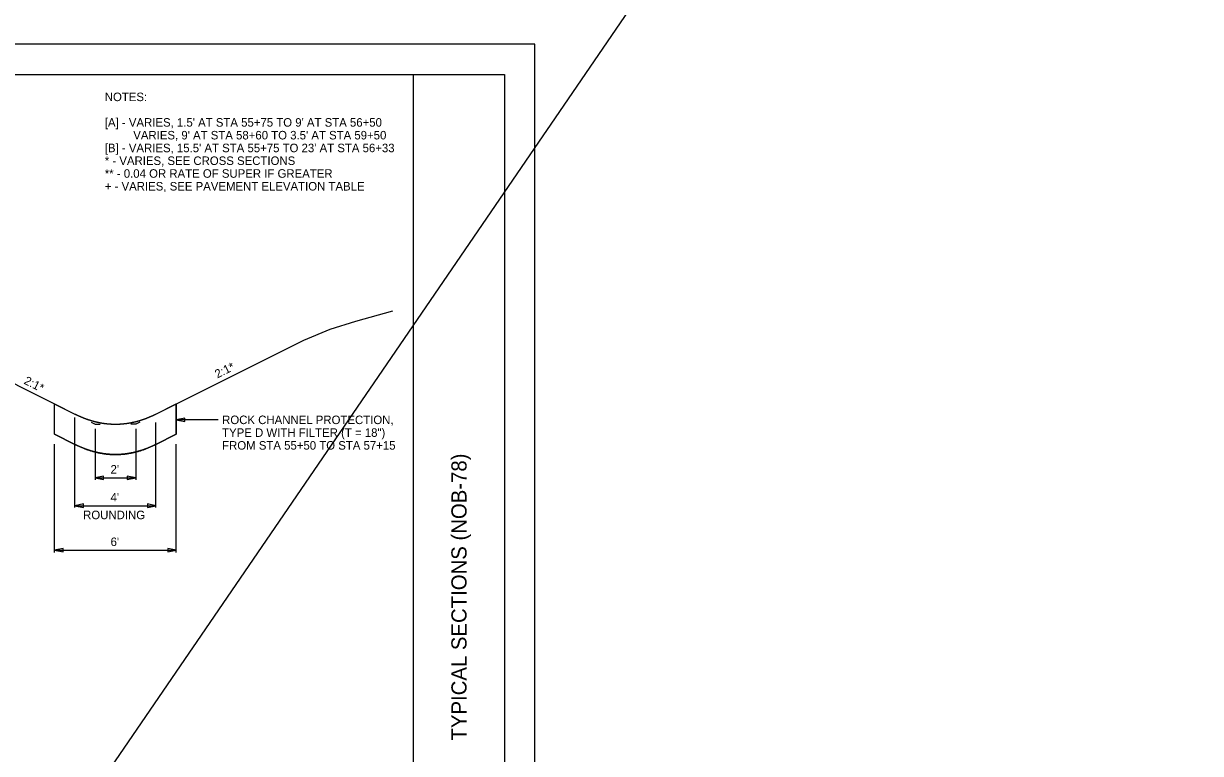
# Model space of a CAD drawing. Extents: x -345 to 102, y -108 to 100.
# Drawn here: x -258.4 to -200.3, y 21.8 to 57.8 of the extents above; entities that cross this region are included whole.
import ezdxf

# ---------------------------------------------------------------- set-up
doc = ezdxf.new("R2010")
doc.units = 0
for name, color, linetype in [('DR_P_Erosion_Control', 7, 'Continuous'), ('DT_X_Terrain_Ground_Line', 7, 'Continuous'), ('SH_Border', 7, 'Continuous'), ('SH_Cut_Line', 7, 'Continuous'), ('SH_Data', 7, 'Continuous'), ('TX_P_1', 7, 'Continuous'), ('TX_X_1', 7, 'Continuous'), ('XS_P_Finished_Grade', 7, 'Continuous')]:
    doc.layers.add(name, color=color, linetype=linetype)

msp = doc.modelspace()

# ---------------------------------------------------------------- linework, layer by layer
at = {"layer": 'DR_P_Erosion_Control'}
for p, q in [((-256.838, 37.548), (-256.838, 39.048)), ((-250.838, 37.548), (-250.838, 39.048)), ((-256.838, 37.548), (-255.838, 37.048)), ((-251.838, 37.048), (-250.838, 37.548))]:
    msp.add_line(p, q, dxfattribs=at)
for points in [[(-255.838, 37.048), (-256.838, 37.548), (-256.838, 39.048), (-255.838, 38.548)], [(-251.838, 38.548), (-250.838, 39.048), (-250.838, 37.548), (-251.838, 37.048)]]:
    msp.add_lwpolyline(points, dxfattribs=at)
for points in [[(-255.838, 38.548), (-255.813, 38.535), (-255.787, 38.523), (-255.761, 38.51), (-255.736, 38.498), (-255.71, 38.486), (-255.684, 38.474), (-255.659, 38.462), (-255.633, 38.451), (-255.607, 38.439), (-255.582, 38.428), (-255.556, 38.417), (-255.53, 38.406), (-255.505, 38.395), (-255.479, 38.385), (-255.453, 38.374), (-255.428, 38.364), (-255.402, 38.354), (-255.377, 38.344), (-255.351, 38.334), (-255.325, 38.324), (-255.3, 38.315), (-255.274, 38.306), (-255.248, 38.297), (-255.223, 38.288), (-255.197, 38.279), (-255.171, 38.27), (-255.146, 38.262), (-255.12, 38.253), (-255.095, 38.245), (-255.069, 38.237), (-255.043, 38.23), (-255.018, 38.222), (-254.992, 38.214), (-254.966, 38.207), (-254.941, 38.2), (-254.915, 38.193), (-254.889, 38.186), (-254.864, 38.179), (-254.838, 38.173), (-254.812, 38.167), (-254.787, 38.16), (-254.761, 38.155), (-254.736, 38.149), (-254.71, 38.143), (-254.684, 38.138), (-254.659, 38.132), (-254.633, 38.127), (-254.607, 38.122), (-254.582, 38.117), (-254.556, 38.112), (-254.53, 38.108), (-254.505, 38.104), (-254.479, 38.099), (-254.453, 38.095), (-254.428, 38.091), (-254.402, 38.088), (-254.377, 38.084), (-254.351, 38.081), (-254.325, 38.078), (-254.3, 38.075), (-254.274, 38.072), (-254.248, 38.069), (-254.223, 38.067), (-254.197, 38.064), (-254.171, 38.062), (-254.146, 38.06), (-254.12, 38.058), (-254.094, 38.056), (-254.069, 38.055), (-254.043, 38.053), (-254.018, 38.052), (-253.992, 38.051), (-253.966, 38.05), (-253.941, 38.049), (-253.915, 38.049), (-253.889, 38.048), (-253.864, 38.048), (-253.838, 38.048), (-253.812, 38.048), (-253.787, 38.048), (-253.761, 38.049), (-253.735, 38.049), (-253.71, 38.05), (-253.684, 38.051), (-253.659, 38.052), (-253.633, 38.053), (-253.607, 38.055), (-253.582, 38.056), (-253.556, 38.058), (-253.53, 38.06), (-253.505, 38.062), (-253.479, 38.064), (-253.453, 38.067), (-253.428, 38.069), (-253.402, 38.072), (-253.377, 38.075), (-253.351, 38.078), (-253.325, 38.081), (-253.3, 38.084), (-253.274, 38.088), (-253.248, 38.091), (-253.223, 38.095), (-253.197, 38.099), (-253.171, 38.104), (-253.146, 38.108), (-253.12, 38.112), (-253.094, 38.117), (-253.069, 38.122), (-253.043, 38.127), (-253.018, 38.132), (-252.992, 38.138), (-252.966, 38.143), (-252.941, 38.149), (-252.915, 38.155), (-252.889, 38.16), (-252.864, 38.167), (-252.838, 38.173), (-252.812, 38.179), (-252.787, 38.186), (-252.761, 38.193), (-252.735, 38.2), (-252.71, 38.207), (-252.684, 38.214), (-252.659, 38.222), (-252.633, 38.23), (-252.607, 38.237), (-252.582, 38.245), (-252.556, 38.253), (-252.53, 38.262), (-252.505, 38.27), (-252.479, 38.279), (-252.453, 38.288), (-252.428, 38.297), (-252.402, 38.306), (-252.377, 38.315), (-252.351, 38.324), (-252.325, 38.334), (-252.3, 38.344), (-252.274, 38.354), (-252.248, 38.364), (-252.223, 38.374), (-252.197, 38.385), (-252.171, 38.395), (-252.146, 38.406), (-252.12, 38.417), (-252.094, 38.428), (-252.069, 38.439), (-252.043, 38.451), (-252.017, 38.462), (-251.992, 38.474), (-251.966, 38.486), (-251.941, 38.498), (-251.915, 38.51), (-251.889, 38.523), (-251.864, 38.535), (-251.838, 38.548)], [(-251.838, 37.048), (-251.864, 37.035), (-251.889, 37.023), (-251.915, 37.01), (-251.941, 36.998), (-251.966, 36.986), (-251.992, 36.974), (-252.017, 36.962), (-252.043, 36.951), (-252.069, 36.939), (-252.094, 36.928), (-252.12, 36.917), (-252.146, 36.906), (-252.171, 36.895), (-252.197, 36.885), (-252.223, 36.874), (-252.248, 36.864), (-252.274, 36.854), (-252.3, 36.844), (-252.325, 36.834), (-252.351, 36.824), (-252.377, 36.815), (-252.402, 36.806), (-252.428, 36.797), (-252.453, 36.788), (-252.479, 36.779), (-252.505, 36.77), (-252.53, 36.762), (-252.556, 36.753), (-252.582, 36.745), (-252.607, 36.737), (-252.633, 36.73), (-252.659, 36.722), (-252.684, 36.714), (-252.71, 36.707), (-252.735, 36.7), (-252.761, 36.693), (-252.787, 36.686), (-252.812, 36.679), (-252.838, 36.673), (-252.864, 36.667), (-252.889, 36.66), (-252.915, 36.655), (-252.941, 36.649), (-252.966, 36.643), (-252.992, 36.638), (-253.018, 36.632), (-253.043, 36.627), (-253.069, 36.622), (-253.094, 36.617), (-253.12, 36.612), (-253.146, 36.608), (-253.171, 36.604), (-253.197, 36.599), (-253.223, 36.595), (-253.248, 36.591), (-253.274, 36.588), (-253.3, 36.584), (-253.325, 36.581), (-253.351, 36.578), (-253.377, 36.575), (-253.402, 36.572), (-253.428, 36.569), (-253.453, 36.567), (-253.479, 36.564), (-253.505, 36.562), (-253.53, 36.56), (-253.556, 36.558), (-253.582, 36.556), (-253.607, 36.555), (-253.633, 36.553), (-253.659, 36.552), (-253.684, 36.551), (-253.71, 36.55), (-253.735, 36.549), (-253.761, 36.549), (-253.787, 36.548), (-253.812, 36.548), (-253.838, 36.548), (-253.864, 36.548), (-253.889, 36.548), (-253.915, 36.549), (-253.941, 36.549), (-253.966, 36.55), (-253.992, 36.551), (-254.018, 36.552), (-254.043, 36.553), (-254.069, 36.555), (-254.094, 36.556), (-254.12, 36.558), (-254.146, 36.56), (-254.171, 36.562), (-254.197, 36.564), (-254.223, 36.567), (-254.248, 36.569), (-254.274, 36.572), (-254.3, 36.575), (-254.325, 36.578), (-254.351, 36.581), (-254.377, 36.584), (-254.402, 36.588), (-254.428, 36.591), (-254.453, 36.595), (-254.479, 36.599), (-254.505, 36.604), (-254.53, 36.608), (-254.556, 36.612), (-254.582, 36.617), (-254.607, 36.622), (-254.633, 36.627), (-254.659, 36.632), (-254.684, 36.638), (-254.71, 36.643), (-254.736, 36.649), (-254.761, 36.655), (-254.787, 36.66), (-254.812, 36.667), (-254.838, 36.673), (-254.864, 36.679), (-254.889, 36.686), (-254.915, 36.693), (-254.941, 36.7), (-254.966, 36.707), (-254.992, 36.714), (-255.018, 36.722), (-255.043, 36.73), (-255.069, 36.737), (-255.095, 36.745), (-255.12, 36.753), (-255.146, 36.762), (-255.171, 36.77), (-255.197, 36.779), (-255.223, 36.788), (-255.248, 36.797), (-255.274, 36.806), (-255.3, 36.815), (-255.325, 36.824), (-255.351, 36.834), (-255.377, 36.844), (-255.402, 36.854), (-255.428, 36.864), (-255.453, 36.874), (-255.479, 36.885), (-255.505, 36.895), (-255.53, 36.906), (-255.556, 36.917), (-255.582, 36.928), (-255.607, 36.939), (-255.633, 36.951), (-255.659, 36.962), (-255.684, 36.974), (-255.71, 36.986), (-255.736, 36.998), (-255.761, 37.01), (-255.787, 37.023), (-255.813, 37.035), (-255.838, 37.048)]]:
    msp.add_open_spline(points, degree=3, dxfattribs=at)
msp.add_spline([(-255.838, 37.048), (-255.761, 37.01), (-255.684, 36.974), (-255.607, 36.939), (-255.53, 36.906), (-255.453, 36.874), (-255.377, 36.844), (-255.3, 36.815), (-255.223, 36.788), (-255.146, 36.762), (-255.069, 36.737), (-254.992, 36.714), (-254.915, 36.693), (-254.838, 36.673), (-254.761, 36.655), (-254.684, 36.638), (-254.607, 36.622), (-254.53, 36.608), (-254.453, 36.595), (-254.377, 36.584), (-254.3, 36.575), (-254.223, 36.567), (-254.146, 36.56), (-254.069, 36.555), (-253.992, 36.551), (-253.915, 36.549), (-253.838, 36.548), (-253.761, 36.549), (-253.684, 36.551), (-253.607, 36.555), (-253.53, 36.56), (-253.453, 36.567), (-253.377, 36.575), (-253.3, 36.584), (-253.223, 36.595), (-253.146, 36.608), (-253.069, 36.622), (-252.992, 36.638), (-252.915, 36.655), (-252.838, 36.673), (-252.761, 36.693), (-252.684, 36.714), (-252.607, 36.737), (-252.53, 36.762), (-252.453, 36.788), (-252.377, 36.815), (-252.3, 36.844), (-252.223, 36.874), (-252.146, 36.906), (-252.069, 36.939), (-251.992, 36.974), (-251.915, 37.01), (-251.838, 37.048)], degree=3, dxfattribs=at)
at = {"layer": 'DT_X_Terrain_Ground_Line'}
msp.add_lwpolyline([(-244.547, 42.194), (-243.249, 42.729), (-241.974, 43.126), (-240.149, 43.631)], dxfattribs=at)
at = {"layer": 'SH_Border'}
msp.add_line((-239.144, -7.702), (-239.144, 55.298), dxfattribs=at)
msp.add_lwpolyline([(-330.644, 55.298), (-234.644, 55.298), (-234.644, -7.702), (-330.644, -7.702)], close=True, dxfattribs=at)
at = {"layer": 'SH_Cut_Line'}
msp.add_lwpolyline([(-335.144, -9.202), (-233.144, -9.202), (-233.144, 56.798), (-335.144, 56.798)], close=True, dxfattribs=at)
at = {"layer": 'TX_P_1'}
for p, q in [((-255.838, 33.931), (-255.838, 38.37)), ((-250.418, 38.176), (-250.418, 38.344)), ((-254.838, 37.81), (-254.838, 35.297)), ((-252.838, 37.81), (-252.838, 35.297)), ((-251.838, 33.931), (-251.838, 38.125)), ((-256.838, 31.71), (-256.838, 37.059)), ((-250.838, 31.71), (-250.838, 37.059)), ((-254.418, 35.316), (-254.418, 35.484)), ((-253.258, 35.484), (-253.258, 35.316)), ((-254.838, 35.4), (-252.838, 35.4)), ((-255.838, 34.025), (-251.838, 34.025)), ((-255.418, 33.941), (-255.418, 34.109)), ((-252.258, 34.109), (-252.258, 33.941)), ((-256.838, 31.825), (-250.838, 31.825)), ((-256.418, 31.741), (-256.418, 31.909)), ((-251.258, 31.909), (-251.258, 31.741))]:
    msp.add_line(p, q, dxfattribs=at)
for points in [[(-250.418, 38.344), (-250.838, 38.26), (-250.418, 38.176)], [(-255.041, 38.149), (-254.838, 38.048), (-254.596, 38.048)], [(-252.635, 38.149), (-252.838, 38.048), (-253.08, 38.048)], [(-254.418, 35.484), (-254.838, 35.4), (-254.418, 35.316)], [(-253.258, 35.316), (-252.838, 35.4), (-253.258, 35.484)], [(-255.418, 34.109), (-255.838, 34.025), (-255.418, 33.941)], [(-252.258, 33.941), (-251.838, 34.025), (-252.258, 34.109)], [(-256.418, 31.909), (-256.838, 31.825), (-256.418, 31.741)], [(-251.258, 31.741), (-250.838, 31.825), (-251.258, 31.909)]]:
    msp.add_lwpolyline(points, dxfattribs=at)
at = {"layer": 'TX_X_1'}
for p, q in [((-200.323, 99.689), (-335.9, -98.481)), ((-248.773, 38.26), (-250.838, 38.26))]:
    msp.add_line(p, q, dxfattribs=at)
at = {"layer": 'XS_P_Finished_Grade'}
for p, q in [((-251.838, 38.548), (-244.547, 42.194)), ((-260.075, 40.667), (-255.838, 38.548))]:
    msp.add_line(p, q, dxfattribs=at)
msp.add_spline([(-255.838, 38.548), (-255.761, 38.51), (-255.684, 38.474), (-255.607, 38.439), (-255.53, 38.406), (-255.453, 38.374), (-255.377, 38.344), (-255.3, 38.315), (-255.223, 38.288), (-255.146, 38.262), (-255.069, 38.237), (-254.992, 38.214), (-254.915, 38.193), (-254.838, 38.173), (-254.761, 38.155), (-254.684, 38.138), (-254.607, 38.122), (-254.53, 38.108), (-254.453, 38.095), (-254.377, 38.084), (-254.3, 38.075), (-254.223, 38.067), (-254.146, 38.06), (-254.069, 38.055), (-253.992, 38.051), (-253.915, 38.049), (-253.838, 38.048), (-253.761, 38.049), (-253.684, 38.051), (-253.607, 38.055), (-253.53, 38.06), (-253.453, 38.067), (-253.377, 38.075), (-253.3, 38.084), (-253.223, 38.095), (-253.146, 38.108), (-253.069, 38.122), (-252.992, 38.138), (-252.915, 38.155), (-252.838, 38.173), (-252.761, 38.193), (-252.684, 38.214), (-252.607, 38.237), (-252.53, 38.262), (-252.453, 38.288), (-252.377, 38.315), (-252.3, 38.344), (-252.223, 38.374), (-252.146, 38.406), (-252.069, 38.439), (-251.992, 38.474), (-251.915, 38.51), (-251.838, 38.548)], degree=3, dxfattribs=at)

# ---------------------------------------------------------------- texts
at = {"layer": 'SH_Data'}
msp.add_text('TYPICAL SECTIONS (NOB-78)', height=0.75, rotation=90, dxfattribs=at).set_placement((-236.519, 22.442))
at = {"layer": 'TX_P_1'}
for rotation, p in [(26.56505, (-248.81, 40.297)), (333.43495, (-258.386, 40.057))]:
    msp.add_text('2:1*', height=0.42, rotation=rotation, dxfattribs=at).set_placement(p)
for s, p in [("2'", (-254.077, 35.61)), ("4'", (-254.077, 34.235)), ('ROUNDING', (-255.432, 33.359)), ("6'", (-254.077, 32.035))]:
    msp.add_text(s, height=0.42, dxfattribs=at).set_placement(p)
at = {"layer": 'TX_X_1'}
for s, p in [('NOTES:', (-254.362, 53.983)), ("[A] - VARIES, 1.5' AT STA 55+75 TO 9' AT STA 56+50", (-254.362, 52.723)), ("         VARIES, 9' AT STA 58+60 TO 3.5' AT STA 59+50", (-254.362, 52.093)), ("[B] - VARIES, 15.5' AT STA 55+75 TO 23' AT STA 56+33", (-254.362, 51.463)), ('* - VARIES, SEE CROSS SECTIONS', (-254.362, 50.833)), ('** - 0.04 OR RATE OF SUPER IF GREATER', (-254.362, 50.203)), ('+ - VARIES, SEE PAVEMENT ELEVATION TABLE', (-254.362, 49.573)), ('ROCK CHANNEL PROTECTION,', (-248.575, 38.05)), ('TYPE D WITH FILTER (T = 18")', (-248.575, 37.42)), ('FROM STA 55+50 TO STA 57+15', (-248.575, 36.79))]:
    msp.add_text(s, height=0.42, dxfattribs=at).set_placement(p)

doc.saveas('drawing.dxf')
